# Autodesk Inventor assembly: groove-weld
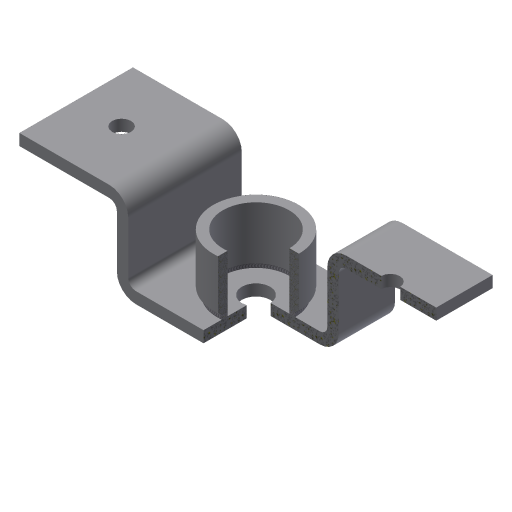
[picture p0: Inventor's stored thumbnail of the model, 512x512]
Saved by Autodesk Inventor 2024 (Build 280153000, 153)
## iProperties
Created: 2005-03
Part Number: groove-weld
Document SubType Name: Weldment
Designer: CADCIM
Manufacturer: Standard
Standards Organization: Custom
Author: CADCIM
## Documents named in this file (3)
- D:\PROJECTS\Project 2023\RESOURCES INVENTOR 2024\RESOURCES INVENTOR 2024\Inventor_2023_Part\Inventor_2024_Part\c16_Inv_2024_prt\fig 16-16\groove-weld.iam
- D:\PROJECTS\Project 2023\RESOURCES INVENTOR 2024\RESOURCES INVENTOR 2024\Inventor_2023_Part\Inventor_2024_Part\c16_Inv_2024_prt\fig 16-16\Bracket.ipt
- D:\PROJECTS\Project 2023\RESOURCES INVENTOR 2024\RESOURCES INVENTOR 2024\Inventor_2023_Part\Inventor_2024_Part\c16_Inv_2024_prt\fig 16-16\cylinder.ipt
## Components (2 placed, 2 different names)
1. Bracket:1 — Insert:1
2. cylinder:1 — Insert:1
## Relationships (1: Insert 1)
- Insert:1: Bracket:1 ↔ cylinder:1
